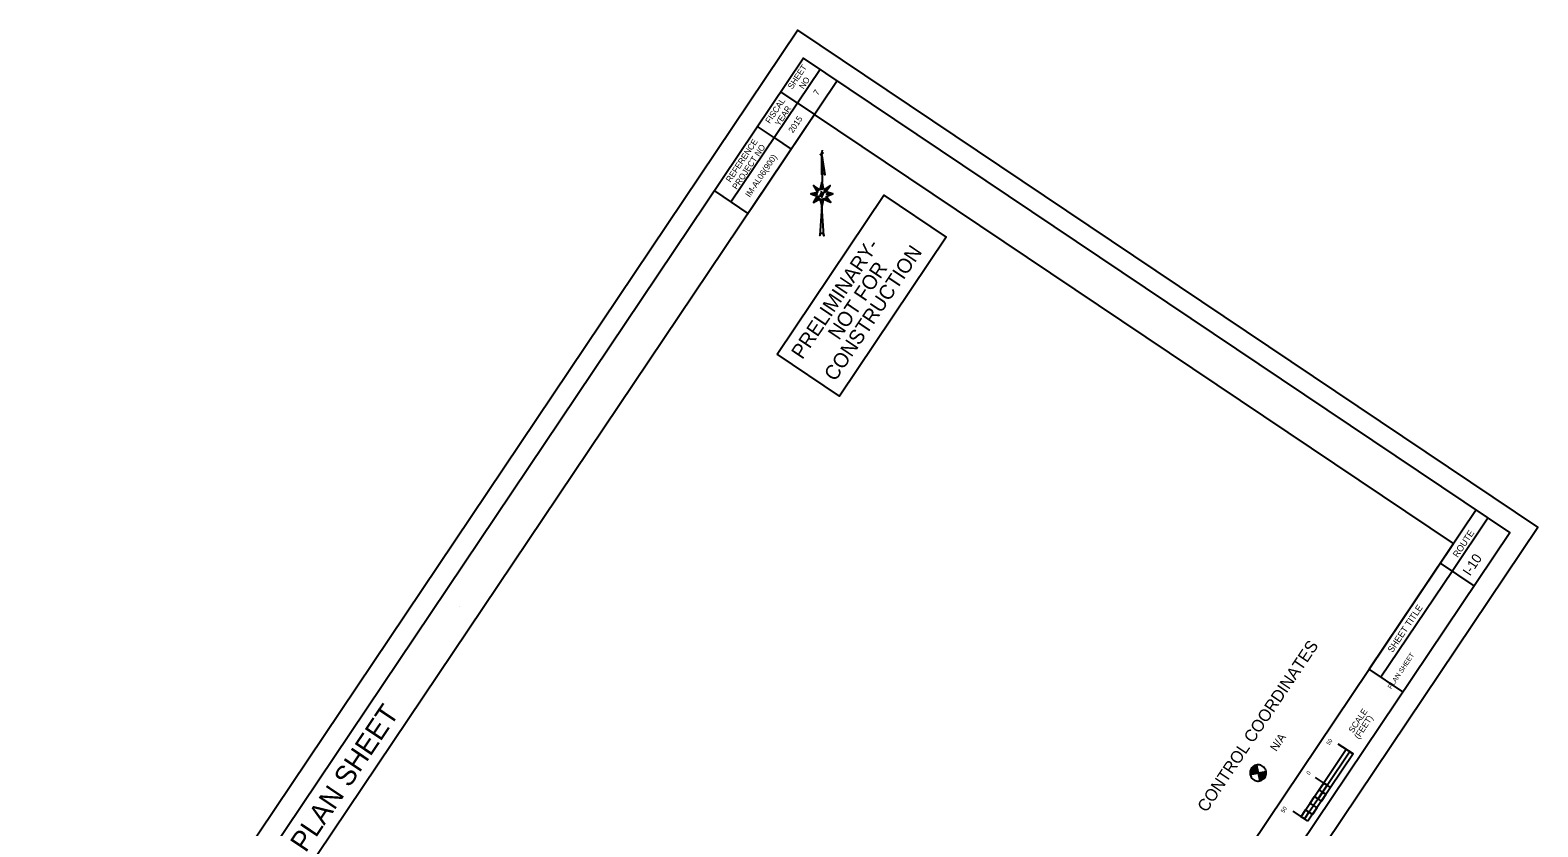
# Model space of a CAD drawing. Extents: x 1797253 to 1799113, y 249374 to 251399.
# Drawn here: x 1797253 to 1799113, y 250416 to 251399 of the extents above; entities that cross this region are included whole.
import ezdxf

# ---------------------------------------------------------------- set-up
doc = ezdxf.new("R2010")
doc.units = 0
for name, color, linetype in [('1', 7, 'Continuous'), ('ANNO-SHT', 7, 'Continuous'), ('ANNO-SYMB', 7, 'Continuous'), ('ANNO-TXT', 7, 'Continuous'), ('CLOSURE', 7, 'Continuous'), ('Default', 7, 'Continuous'), ('DRAINAGE', 7, 'Continuous'), ('Level 1', 7, 'Continuous'), ('Level 31', 7, 'Continuous'), ('Level 45', 7, 'Continuous'), ('Level 57', 7, 'Continuous'), ('Level 6', 7, 'Continuous'), ('Level 62', 7, 'Continuous'), ('SHT-BDR', 7, 'Continuous'), ('SHT-BNDRY', 7, 'Continuous')]:
    doc.layers.add(name, color=color, linetype=linetype)

# ---------------------------------------------------------------- blocks, each defined once
blk = doc.blocks.new('SC47208')
at = {"layer": 'Level 1'}
blk.add_line((0, 0), (0, 0), dxfattribs=at)
blk = doc.blocks.new('POINT_DISPLAY')
at = {"layer": 'Default'}
blk.add_line((0, 0), (0, 0), dxfattribs=at)

msp = doc.modelspace()

# ---------------------------------------------------------------- linework, layer by layer
at = {"layer": '1'}
msp.add_lwpolyline([(1798174.6, 250998.9), (1798306.4, 251195.2), (1798383.3, 251143.5), (1798251.5, 250947.3)], close=True, dxfattribs=at)
at = {"layer": 'ANNO-SYMB'}
for p, q in [((1798877, 250511.2), (1798821.2, 250428.2)), ((1798885.3, 250505.6), (1798867, 250517.9)), ((1798885.3, 250505.6), (1798829.5, 250422.6)), ((1798885.3, 250505.6), (1798881.1, 250508.4)), ((1798885.3, 250505.6), (1798881.1, 250508.4)), ((1798885.3, 250505.6), (1798881.1, 250508.4)), ((1798857.4, 250464.1), (1798839.1, 250476.4)), ((1798857.4, 250464.1), (1798839.1, 250476.4)), ((1798857.4, 250464.1), (1798839.1, 250476.4)), ((1798853.2, 250466.9), (1798842.1, 250450.3)), ((1798853.2, 250466.9), (1798849.1, 250469.7)), ((1798853.2, 250466.9), (1798849.1, 250469.7)), ((1798853.2, 250466.9), (1798849.1, 250469.7)), ((1798829.5, 250422.6), (1798811.3, 250434.9)), ((1798830.9, 250433.7), (1798826.8, 250436.5)), ((1798830.9, 250433.7), (1798826.8, 250436.5))]:
    msp.add_line(p, q, dxfattribs=at)
for points in [[(1798853.2, 250466.9), (1798881.1, 250508.4), (1798885.3, 250505.6), (1798857.4, 250464.1)], [(1798842.1, 250450.3), (1798847.7, 250458.6), (1798851.8, 250455.8), (1798846.2, 250447.5)], [(1798843.5, 250461.4), (1798849.1, 250469.7), (1798853.2, 250466.9), (1798847.7, 250458.6)], [(1798830.9, 250433.7), (1798836.5, 250442), (1798840.7, 250439.2), (1798835.1, 250430.9)], [(1798832.4, 250444.8), (1798837.9, 250453.1), (1798842.1, 250450.3), (1798836.5, 250442)], [(1798821.2, 250428.2), (1798826.8, 250436.5), (1798830.9, 250433.7), (1798825.4, 250425.4)]]:
    msp.add_lwpolyline(points, close=True, dxfattribs=at)
at = {"layer": 'ANNO-TXT'}
for p, q in [((1799007.5, 250731.4), (1799051.6, 250797.1)), ((1798919.6, 250600.6), (1799007.5, 250731.4))]:
    msp.add_line(p, q, dxfattribs=at)
at = {"layer": 'CLOSURE'}
for p, q in [((1798758.4, 250484.2), (1798758.2, 250482.7)), ((1798758.2, 250482.7), (1798758.2, 250481.2)), ((1798758.2, 250481.2), (1798758.5, 250479.7)), ((1798758.8, 250485.7), (1798758.4, 250484.2)), ((1798758.5, 250480.2), (1798777.9, 250484.1)), ((1798758.5, 250479.7), (1798759, 250478.2)), ((1798759.5, 250487.1), (1798758.8, 250485.7)), ((1798758.9, 250482), (1798760.8, 250480.7)), ((1798759, 250483.5), (1798762.6, 250481.1)), ((1798759, 250478.2), (1798759.7, 250476.9)), ((1798759.2, 250485), (1798764.5, 250481.4)), ((1798760.3, 250488.3), (1798759.5, 250487.1)), ((1798759.7, 250486.2), (1798766.3, 250481.8)), ((1798759.7, 250476.9), (1798760.6, 250475.6)), ((1798761.4, 250489.5), (1798760.3, 250488.3)), ((1798760.4, 250487.4), (1798776, 250477)), ((1798760.6, 250475.6), (1798761.7, 250474.5)), ((1798761.2, 250488.5), (1798767.8, 250484)), ((1798762.6, 250490.4), (1798761.4, 250489.5)), ((1798761.7, 250474.5), (1798763, 250473.6)), ((1798762.2, 250489.4), (1798767.5, 250485.9)), ((1798763.9, 250491.2), (1798762.6, 250490.4)), ((1798763.5, 250490.1), (1798767.1, 250487.7)), ((1798765.3, 250491.7), (1798763.9, 250491.2)), ((1798764.8, 250490.9), (1798766.7, 250489.6)), ((1798766.8, 250492.1), (1798765.3, 250491.7)), ((1798766.3, 250491.9), (1798770.1, 250472.5)), ((1798768.3, 250492.2), (1798766.8, 250492.1)), ((1798769.9, 250492), (1798768.3, 250492.2)), ((1798775.2, 250475.9), (1798768.6, 250480.3)), ((1798768.9, 250478.5), (1798774.2, 250474.9)), ((1798769.3, 250476.6), (1798772.9, 250474.2)), ((1798769.7, 250474.8), (1798771.6, 250473.5)), ((1798771.4, 250491.7), (1798769.9, 250492)), ((1798776.7, 250478.1), (1798770, 250482.5)), ((1798772.8, 250491.1), (1798771.4, 250491.7)), ((1798771.9, 250482.9), (1798777.2, 250479.4)), ((1798774.1, 250490.3), (1798772.8, 250491.1)), ((1798773.2, 250473.5), (1798774.4, 250474.4)), ((1798773.7, 250483.3), (1798777.3, 250480.9)), ((1798775.2, 250489.3), (1798774.1, 250490.3)), ((1798774.4, 250474.4), (1798775.6, 250475.4)), ((1798776.2, 250488.1), (1798775.2, 250489.3)), ((1798775.6, 250483.6), (1798777.5, 250482.3)), ((1798775.6, 250475.4), (1798776.5, 250476.6)), ((1798777.1, 250486.8), (1798776.2, 250488.1)), ((1798776.5, 250476.6), (1798777.3, 250477.9)), ((1798777.7, 250485.4), (1798777.1, 250486.8)), ((1798777.3, 250477.9), (1798777.8, 250479.4)), ((1798778, 250483.9), (1798777.7, 250485.4)), ((1798777.8, 250479.4), (1798778.1, 250480.9)), ((1798778.2, 250482.4), (1798778, 250483.9)), ((1798778.1, 250480.9), (1798778.2, 250482.4)), ((1798763, 250473.6), (1798764.3, 250472.9)), ((1798764.3, 250472.9), (1798765.8, 250472.5)), ((1798765.8, 250472.5), (1798767.3, 250472.2)), ((1798767.3, 250472.2), (1798768.8, 250472.2)), ((1798768.8, 250472.2), (1798770.3, 250472.4)), ((1798770.3, 250472.4), (1798771.8, 250472.8)), ((1798771.8, 250472.8), (1798773.2, 250473.5))]:
    msp.add_line(p, q, dxfattribs=at)
at = {"layer": 'Level 57'}
msp.add_line((1798229.9, 251250.8), (1798229.7, 251248.3), dxfattribs=at)
for points in [[(1798230.9, 251247.3), (1798230.9, 251247.2), (1798230.9, 251247.1), (1798231, 251247.2), (1798231, 251247.4), (1798230.8, 251247.4), (1798230.5, 251247.2), (1798230.4, 251247.1), (1798230.2, 251246.8), (1798230.1, 251246.3), (1798229.8, 251245.8), (1798229.8, 251245.6), (1798229.7, 251245.2), (1798229.7, 251245.8), (1798229.6, 251246.7), (1798229.4, 251247.4), (1798229.4, 251246.8), (1798229.7, 251245.2), (1798229.6, 251246.8), (1798229.4, 251247.4), (1798229.3, 251246.8), (1798228.9, 251245.8), (1798228.6, 251245.2), (1798228.4, 251245.1), (1798228.1, 251245.1), (1798228, 251245.2), (1798228, 251245.4), (1798228.1, 251245.5), (1798228.2, 251245.4), (1798228.1, 251245.3)], [(1798229.7, 251244.3), (1798233.4, 251220.2), (1798233.3, 251220.9), (1798233.1, 251221.2), (1798232.7, 251221.6), (1798232.1, 251221.8), (1798231.8, 251221.9), (1798231.5, 251221.9), (1798231.1, 251221.9), (1798230.8, 251221.8), (1798230.5, 251221.6), (1798230.1, 251221.4), (1798229.9, 251221.1), (1798229.8, 251220.8), (1798229.8, 251220.7), (1798229.8, 251244.1), (1798229.9, 251211.2)], [(1798229.8, 251211.2), (1798229.7, 251202.3), (1798229.8, 251211.3), (1798227.1, 251201.7), (1798219.2, 251207.2), (1798225.3, 251200.5), (1798219.2, 251207.2), (1798224.2, 251198.7), (1798216.2, 251196.8), (1798223.8, 251196.6), (1798216.3, 251196.9), (1798224, 251194.1), (1798219.5, 251186.3), (1798225.2, 251192), (1798219.5, 251186.3), (1798227.3, 251190.6), (1798229.7, 251181.7), (1798229.6, 251190.1), (1798229.7, 251181.5), (1798231.7, 251190.5), (1798240.6, 251186.4), (1798231.6, 251190.5), (1798229.7, 251181.2), (1798227.3, 251145.3), (1798227.5, 251146.4), (1798227.8, 251147.2), (1798228.3, 251147.7), (1798228.9, 251148.2), (1798229.5, 251148.3), (1798230.1, 251148.3), (1798230.6, 251148.1), (1798231.1, 251147.8), (1798231.5, 251147.2), (1798231.9, 251146.6), (1798232, 251146.1), (1798232.2, 251145.2), (1798229.8, 251181.8), (1798231.5, 251190.6), (1798240.5, 251186.4), (1798233.6, 251191.6), (1798240.3, 251186.5), (1798235.2, 251193.6), (1798243.2, 251196.7), (1798235.5, 251196.6), (1798243.4, 251196.7), (1798234.6, 251199.4), (1798240.1, 251207.2), (1798233.6, 251200.9), (1798240.1, 251207.2), (1798232.1, 251201.7), (1798229.9, 251211.1)], [(1798233.7, 251199.2), (1798233.4, 251199), (1798233.8, 251198.8), (1798233.9, 251199.1), (1798233.8, 251199.5), (1798233.7, 251199.6), (1798233, 251199.5), (1798232.5, 251199.2), (1798231.4, 251198), (1798231.3, 251197.6), (1798230.9, 251196.4), (1798230.5, 251195.1), (1798230, 251194.2), (1798229.8, 251192.8), (1798229.8, 251194.6), (1798229.7, 251196.8), (1798229.6, 251198), (1798229.1, 251199.5), (1798229, 251197.8), (1798229.3, 251195.5), (1798229.5, 251194.1), (1798229.8, 251192.9), (1798229.8, 251194.9), (1798229.6, 251198.1), (1798229, 251199.5), (1798228.7, 251198), (1798228.1, 251196.4), (1798227.8, 251195.8), (1798227.6, 251194.9), (1798227.2, 251194.2), (1798226.9, 251193.6), (1798226.6, 251193.1), (1798225.8, 251192.7), (1798225.2, 251192.8), (1798224.9, 251193.1), (1798224.8, 251193.8), (1798225.2, 251194.1), (1798225.6, 251193.7), (1798225.3, 251193.5)]]:
    msp.add_lwpolyline(points, dxfattribs=at)
at = {"layer": 'Level 6'}
for p, q in [((1798227.5, 251350.4), (1798117.5, 251186.6)), ((1798248.5, 251336.3), (1798141.9, 251177.5)), ((1798199.3, 251309.1), (1798179.1, 251322.6)), ((1798199.3, 251309.1), (1798220.6, 251294.8)), ((1798171.2, 251266), (1798150.4, 251279.9)), ((1798171.2, 251266), (1798191.9, 251252.1)), ((1798097, 251200.4), (1798138.5, 251172.5)), ((1799037.2, 250806.8), (1798905.2, 250610.2))]:
    msp.add_line(p, q, dxfattribs=at)
at = {"layer": 'Level 62'}
msp.add_lwpolyline([(1798165.8, 249374.3), (1799113.4, 250785.7), (1798200.2, 251398.8), (1797252.5, 249987.5)], close=True, dxfattribs=at)
at = {"layer": 'SHT-BDR'}
msp.add_lwpolyline([(1798173.2, 249519.9), (1799009.3, 250765.2), (1798220.6, 251294.8), (1797384.4, 250049.4)], close=True, dxfattribs=at)
at = {"layer": 'SHT-BNDRY'}
for p, q in [((1799034.7, 250713.2), (1798993.1, 250741.1)), ((1798946.8, 250582.3), (1798905.2, 250610.2))]:
    msp.add_line(p, q, dxfattribs=at)
msp.add_lwpolyline([(1798179.9, 249440.1), (1799078.7, 250778.9), (1798207, 251364.2), (1797308.1, 250025.4)], close=True, dxfattribs=at)

# ---------------------------------------------------------------- block references
at = {"layer": 'CLOSURE', "xscale": 1.9999999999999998, "yscale": 1.9999999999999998, "rotation": -33.77794519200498}
msp.add_blockref('POINT_DISPLAY', (1798768.2, 250482.2), dxfattribs=at)
at = {"layer": 'DRAINAGE', "xscale": 1.0000020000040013, "yscale": 1.0000020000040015, "rotation": -60.2945162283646}
msp.add_blockref('SC47208', (1797781.9, 250687.9), dxfattribs=at)
msp.add_blockref('SC47208', (1797781.9, 250687.9), dxfattribs=at)

# ---------------------------------------------------------------- texts
at = {"layer": '1'}
for s, p in [('PRELIMINARY-', (1798205.6, 250991.5)), ('CONSTRUCTION', (1798246.1, 250964.4)), ('NOT FOR', (1798250.9, 251015.3))]:
    msp.add_text(s, height=18, rotation=56.1222, dxfattribs=at).set_placement(p)
at = {"layer": 'ANNO-SHT'}
for s, height, p in [('7', 7.45, (1798224.7, 251317.7)), ('2015', 7.45, (1798193.9, 251271.2)), ('IM-AL06(900)', 7.449, (1798140.8, 251191.9)), ('  I-10  ', 12, (1799024.7, 250717)), ('               PLAN SHEET               ', 6, (1798913.3, 250556.4)), ('               PLAN SHEET               ', 24.998, (1797515, 250267.2))]:
    msp.add_text(s, height=height, rotation=56.1222, dxfattribs=at).set_placement(p)
at = {"layer": 'ANNO-SYMB'}
for s, height, p in [('SCALE', 7.5, (1798885.3, 250531)), ('(FEET)', 7.5, (1798892.4, 250523.3)), (' 50', 5, (1798855, 250514.4)), ('0', 5, (1798831.4, 250479.3)), ('0', 5, (1798831.4, 250479.3)), ('0', 5, (1798831.4, 250479.3)), (' 50', 5, (1798798.8, 250430.7))]:
    msp.add_text(s, height=height, rotation=56.1794, dxfattribs=at).set_placement(p)
at = {"layer": 'ANNO-TXT'}
for s, p in [('ROUTE', (1799014.5, 250747.4)), ('SHEET TITLE', (1798934, 250630))]:
    msp.add_text(s, height=8, rotation=56.1222, dxfattribs=at).set_placement(p)
at = {"layer": 'Level 31'}
msp.add_text('N/A', height=10, rotation=56.1222, dxfattribs=at).set_placement((1798790.6, 250508))
at = {"layer": 'Level 45'}
msp.add_text('CONTROL COORDINATES', height=14.899, rotation=56.1222, dxfattribs=at).set_placement((1798704.4, 250432.6))
at = {"layer": 'Level 6'}
for s, p in [('SHEET', (1798193.2, 251325.4)), ('NO', (1798207.1, 251325.5)), ('FISCAL', (1798165.5, 251282.9)), ('YEAR', (1798177.3, 251279.8)), ('REFERENCE', (1798116.8, 251210.4)), ('PROJECT NO', (1798124.7, 251201.5))]:
    msp.add_text(s, height=7.44, rotation=56.1222, dxfattribs=at).set_placement(p)

doc.saveas('drawing.dxf')
